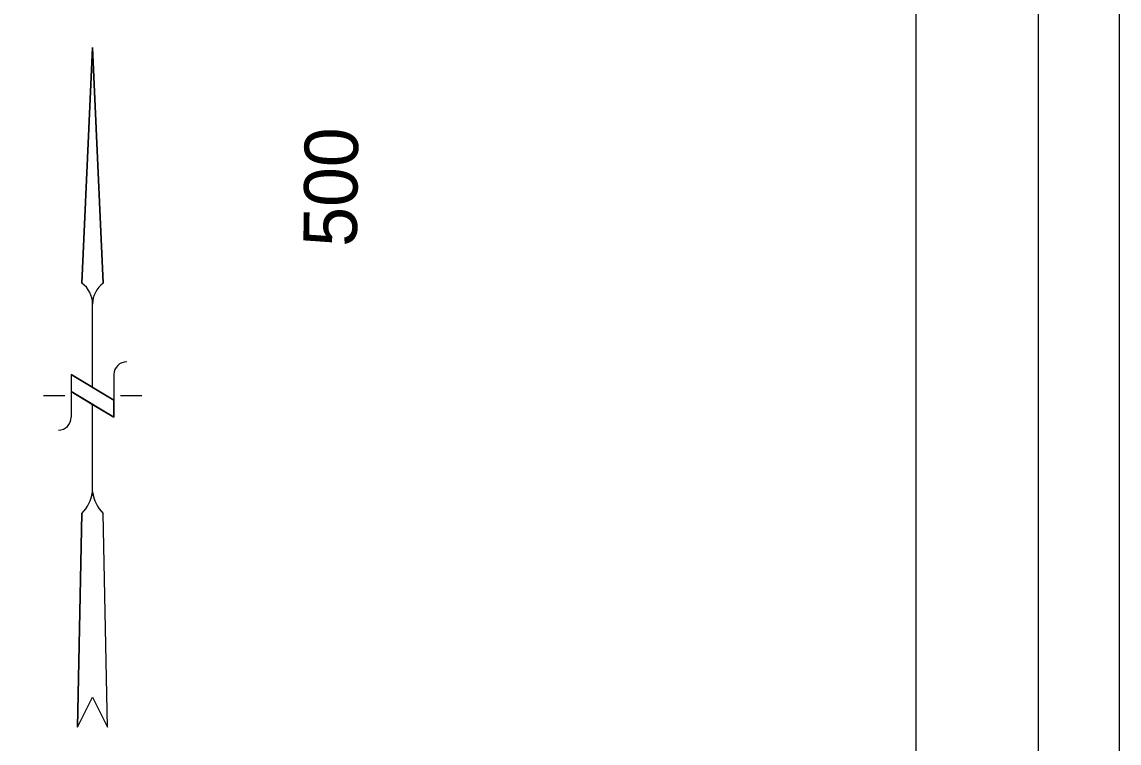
# Model space of a CAD drawing. Extents: x 2150710 to 2158723, y 139737 to 144537.
# Drawn here: x 2157738 to 2158723, y 143242 to 143889 of the extents above; entities that cross this region are included whole.
import ezdxf

# ---------------------------------------------------------------- set-up
doc = ezdxf.new("R2010")
doc.units = 0
for name, color, linetype in [('PR_Txt', 7, 'Continuous'), ('SHT_North_Arrow', 7, 'Continuous'), ('SHT_Plot_Shape_Full', 7, 'Continuous'), ('SHT_Plot_Shape_Half', 7, 'Continuous'), ('SHT_Sheet_Border', 7, 'Continuous')]:
    doc.layers.add(name, color=color, linetype=linetype)

msp = doc.modelspace()

# ---------------------------------------------------------------- linework, layer by layer
at = {"layer": 'SHT_North_Arrow'}
for p, q in [((2157791.36, 143654.71), (2157800.97, 143866.26)), ((2157800.97, 143866.26), (2157791.36, 143654.71)), ((2157800.97, 143866.26), (2157810.59, 143654.71)), ((2157810.59, 143654.71), (2157800.97, 143866.26)), ((2157800.97, 143561.15), (2157800.97, 143635.99)), ((2157820.16, 143549.63), (2157781.78, 143572.66)), ((2157781.78, 143572.66), (2157820.16, 143549.63)), ((2157781.78, 143572.66), (2157781.78, 143534.28)), ((2157800.97, 143561.15), (2157781.78, 143572.66)), ((2157781.78, 143572.66), (2157781.78, 143557.31)), ((2157820.16, 143572.66), (2157820.16, 143534.28)), ((2157820.16, 143549.63), (2157800.97, 143561.15)), ((2157776.02, 143553.47), (2157756.84, 143553.47)), ((2157820.16, 143534.28), (2157781.78, 143557.31)), ((2157820.16, 143534.28), (2157820.16, 143549.63)), ((2157845.11, 143553.47), (2157825.92, 143553.47)), ((2157800.97, 143467.12), (2157800.97, 143545.8)), ((2157787.54, 143256.03), (2157791.38, 143447.93)), ((2157791.38, 143447.93), (2157787.54, 143256.03)), ((2157814.4, 143256.03), (2157810.57, 143447.93)), ((2157814.4, 143256.03), (2157810.57, 143447.93)), ((2157787.54, 143256.03), (2157800.97, 143282.9)), ((2157787.54, 143256.03), (2157800.97, 143282.9)), ((2157800.97, 143282.9), (2157814.4, 143256.03)), ((2157800.97, 143282.9), (2157814.4, 143256.03))]:
    msp.add_line(p, q, dxfattribs=at)
for points in [[(2157781.78, 143557.31), (2157800.97, 143545.8), (2157820.16, 143534.28)], [(2157801, 143467.12), (2157800.97, 143467.12), (2157800.94, 143467.12)]]:
    msp.add_lwpolyline(points, dxfattribs=at)
for centre, radius, start, end in [((2157777.94, 143635.99), 23.03, 0, 54.38016), ((2157777.94, 143635.99), 23.03, 0, 54.38016), ((2157824, 143635.99), 23.03, 125.61984, 180), ((2157824, 143635.99), 23.03, 125.61984, 180), ((2157831.68, 143572.66), 11.51, 90, 180), ((2157770.27, 143534.28), 11.51, 270, 0), ((2157767.56, 143471.78), 33.7, 314.95671, 352.41889), ((2157767.56, 143471.78), 33.7, 314.95671, 352.059), ((2157834.38, 143471.78), 33.7, 187.58111, 225.04329), ((2157834.38, 143471.78), 33.7, 187.941, 225.04329)]:
    msp.add_arc(centre, radius, start, end, dxfattribs=at)
at = {"layer": 'SHT_Plot_Shape_Full'}
msp.add_lwpolyline([(2151522.6, 144536.98), (2158722.6, 144536.98), (2158722.6, 139736.98), (2151522.6, 139736.98)], close=True, dxfattribs=at)
at = {"layer": 'SHT_Plot_Shape_Half'}
msp.add_lwpolyline([(2151850.1, 144371.98), (2158650.1, 144371.98), (2158650.1, 139971.98), (2151850.1, 139971.98)], close=True, dxfattribs=at)
at = {"layer": 'SHT_Sheet_Border'}
msp.add_lwpolyline([(2158540.1, 140071.98), (2152240.1, 140071.98), (2152240.1, 144271.98), (2158540.1, 144271.98)], close=True, dxfattribs=at)

# ---------------------------------------------------------------- texts
at = {"layer": 'PR_Txt'}
msp.add_text('500', height=48, rotation=89.24317, dxfattribs=at).set_placement((2158038.18, 143687.25))

doc.saveas('drawing.dxf')
